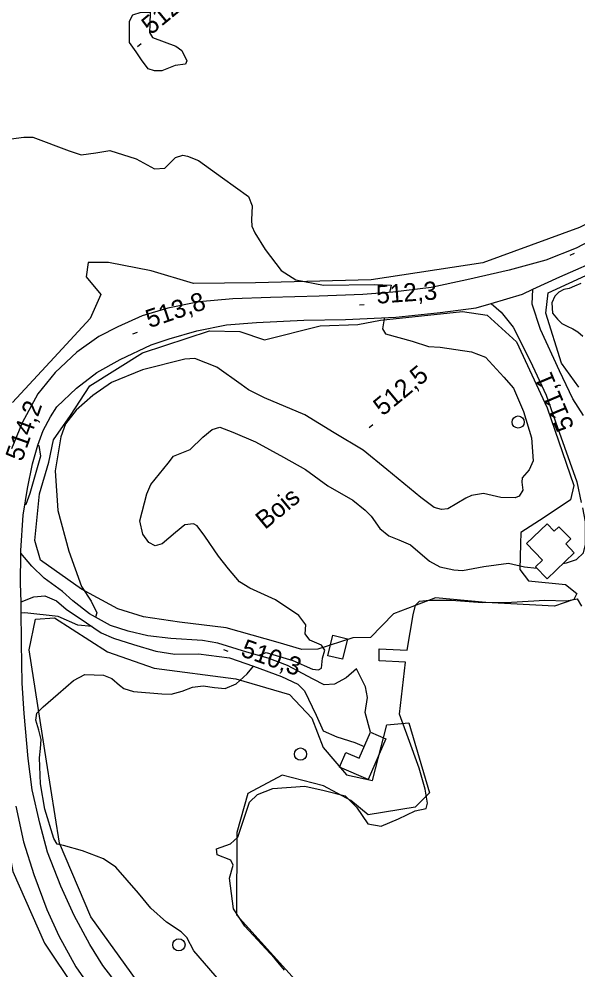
# Model space of a CAD drawing. Extents: x 347059 to 352153, y 6073752 to 6078601.
# Drawn here: x 349153.2 to 349291.1, y 6076824.7 to 6077059.6 of the extents above; entities that cross this region are included whole.
import ezdxf

# ---------------------------------------------------------------- set-up
doc = ezdxf.new("R2010")
doc.units = 0
for name, color, linetype in [('Level 1', 7, 'Continuous'), ('Level 19', 7, 'Continuous'), ('Level 2', 7, 'Continuous'), ('Level 21', 7, 'Continuous'), ('Level 3', 7, 'Continuous'), ('Level 31', 7, 'Continuous'), ('Level 36', 7, 'Continuous'), ('Level 4', 7, 'Continuous'), ('Level 44', 7, 'Continuous')]:
    doc.layers.add(name, color=color, linetype=linetype)

msp = doc.modelspace()

# ---------------------------------------------------------------- linework, layer by layer
at = {"layer": 'Level 1'}
for points in [[(349212.53, 6076902.35), (349212.63, 6076902.53), (349214.21, 6076903.12), (349220.76, 6076901.2), (349220.76, 6076901.2), (349225.61, 6076899.04), (349227.11, 6076898.87), (349227.88, 6076899.29), (349228.1, 6076901.72), (349228.65, 6076903.68), (349227.88, 6076904.98), (349225.01, 6076906.18), (349223.85, 6076907.76), (349223.97, 6076909.96), (349222.27, 6076912.28), (349216.55, 6076916.12), (349210.21, 6076919.07), (349207.66, 6076920.61), (349204.88, 6076923.77), (349202.43, 6076926.97), (349199.09, 6076931.87), (349197.18, 6076934.44), (349196.26, 6076934.88), (349194.1, 6076934.68), (349191.87, 6076932.81), (349188.52, 6076929.99), (349186.78, 6076929.46), (349185.23, 6076930.32), (349183.79, 6076932.34), (349183.05, 6076935.63), (349184.74, 6076942.33), (349185.76, 6076944.67), (349190.05, 6076949.92), (349191.32, 6076951.65), (349195.44, 6076953.24), (349198.58, 6076956.3), (349200.89, 6076958.24), (349202.78, 6076958.76), (349206, 6076957.55), (349211.55, 6076955.2), (349218.45, 6076951.42), (349223.94, 6076948.34), (349229.42, 6076944.31), (349235.61, 6076940.73), (349238.65, 6076938.29), (349240.15, 6076936.84), (349242.24, 6076933.74), (349244.44, 6076931.95), (349246.94, 6076930.94), (349249.79, 6076929.69), (349254.54, 6076925.71), (349257.08, 6076924.33), (349260.48, 6076923.54), (349262.69, 6076923.37), (349267.88, 6076924.36), (349274.01, 6076925.19), (349277.93, 6076924.29), (349281.02, 6076923.96)], [(349287.42, 6076925.09), (349288.32, 6076925.26), (349290.81, 6076926.14), (349292.51, 6076927.79), (349292.98, 6076929.84), (349292.97, 6076935.37), (349292.36, 6076938.9)], [(349209.53, 6076897.84), (349211.1, 6076899.75)], [(349204.27, 6076820.36), (349196.35, 6076829.46), (349194.66, 6076832.77), (349193.24, 6076834.2), (349189.63, 6076836.58), (349185.71, 6076839.99), (349185.71, 6076839.99), (349182.72, 6076843.68), (349177.09, 6076850.15), (349174.03, 6076852.16), (349168.9, 6076854.19), (349164.22, 6076855.52), (349162.62, 6076855.79), (349161.79, 6076857.25), (349159.63, 6076864.47), (349158.55, 6076870.72), (349158.3, 6076877.12), (349158.51, 6076879.45), (349158.66, 6076881.64), (349158.09, 6076883.96), (349157.35, 6076886.44), (349157.65, 6076888.18), (349159.19, 6076889.74), (349162.86, 6076892.97), (349166.68, 6076896.19), (349169.47, 6076897.73), (349174.1, 6076897.58), (349176.09, 6076896.69), (349178.01, 6076895.07), (349179.12, 6076894.24), (349181.49, 6076893.54), (349188.44, 6076892.91), (349190.8, 6076892.87), (349193.45, 6076893.61), (349196.04, 6076894.58), (349198.65, 6076894.89), (349201.42, 6076894.52), (349204.12, 6076894.23), (349206.81, 6076895.41), (349209.53, 6076897.84)]]:
    msp.add_lwpolyline(points, dxfattribs=at)
at = {"layer": 'Level 19'}
for points in [[(349292.55, 6076961.69), (349289.88, 6076965.82), (349286.6, 6076972.67), (349281.89, 6076982.88), (349279.82, 6076989.17), (349280.01, 6076992.83)], [(349269.74, 6076989.34), (349272.17, 6076987.18), (349275.17, 6076983.47), (349279.37, 6076975.15), (349283.31, 6076966.68), (349286.07, 6076958.74), (349290.9, 6076945.32), (349291.97, 6076940.15)], [(349239.94, 6076883.47), (349238.6, 6076888.35), (349239.19, 6076892.06), (349238.69, 6076894.65), (349236.5, 6076899.1), (349233.92, 6076896.88), (349231.09, 6076895.33), (349228.54, 6076895.15), (349225.78, 6076896.59), (349219.48, 6076899.95), (349214.67, 6076901.78), (349209.45, 6076903.19), (349202.28, 6076905.44), (349198.51, 6076906.1), (349190.69, 6076906.61), (349185.04, 6076907.28), (349180.17, 6076908.38), (349175.82, 6076909.83), (349170.62, 6076912.68), (349166.48, 6076915.87), (349163.96, 6076918.19), (349159.46, 6076921.46), (349156.36, 6076924.47), (349153.68, 6076927.66)], [(349153.73, 6076915.62), (349156.86, 6076916.93), (349159.61, 6076917.13), (349162.51, 6076915.88), (349164.89, 6076913.83), (349169.91, 6076910.47), (349173.51, 6076908.02), (349176.53, 6076906.72), (349181.47, 6076905.09), (349186.95, 6076903.45), (349191.65, 6076902.74), (349197.49, 6076902.82), (349205.14, 6076901.8), (349211.11, 6076899.75), (349218.01, 6076897.2), (349222.04, 6076895.32), (349223.68, 6076893.7), (349226.56, 6076887.7), (349228.28, 6076883.82), (349231.61, 6076882.33), (349236.05, 6076880.94), (349238.39, 6076879.89)]]:
    msp.add_lwpolyline(points, dxfattribs=at)
at = {"layer": 'Level 2'}
for points in [[(349182.12, 6077051.51), (349180.49, 6077053.75), (349180.45, 6077059.04), (349181.32, 6077060.59), (349183.38, 6077061.27), (349185.58, 6077061.23), (349185.51, 6077058.25), (349185.41, 6077056.21), (349186.19, 6077054.99), (349191.91, 6077052.87), (349193.36, 6077051.84), (349194.67, 6077049.26), (349194.27, 6077048.39), (349191.75, 6077048.09), (349188.45, 6077046.75), (349186.65, 6077046.75), (349185.11, 6077047.26), (349183.44, 6077049.46), (349182.12, 6077051.51)], [(349146.82, 6077029.41), (349154.42, 6077030.43), (349156.62, 6077030.4), (349165.56, 6077027), (349168.57, 6077026.07), (349172.21, 6077026.56), (349175.64, 6077027.11), (349182.09, 6077025.01), (349186.64, 6077022.59), (349189.22, 6077022.72), (349191.83, 6077025.35), (349193.63, 6077025.96), (349194.83, 6077025.69), (349197.55, 6077024.66), (349203.47, 6077020.4), (349209.85, 6077015.76), (349210.74, 6077013.43), (349210.58, 6077010.01), (349210.64, 6077008.4), (349211.42, 6077006.74), (349213.98, 6077002.66), (349217.9, 6076997.47), (349221.52, 6076995.18), (349228.36, 6076993.86), (349240.96, 6076993.98), (349245.07, 6076993.89), (349244.68, 6076992.03)], [(349291.82, 6076994.3), (349290.31, 6076993.6), (349288.96, 6076993.05), (349287.64, 6076992.82), (349286.45, 6076992.09), (349285.48, 6076991.1), (349284.7, 6076989.53), (349284.83, 6076986.9), (349286.09, 6076985.42), (349287.15, 6076984.36), (349288.48, 6076983.69), (349289.9, 6076983.09), (349291.14, 6076982.34), (349292.36, 6076981.27)], [(349243.4, 6076985.85), (349243.23, 6076985.02), (349242.92, 6076983.04)], [(349242.92, 6076983.04), (349243.67, 6076981.87), (349250.26, 6076980.04), (349254.25, 6076978.74), (349257.17, 6076978.55), (349264.84, 6076977.41), (349268.34, 6076976.06), (349272.85, 6076971.15), (349275.25, 6076968.44), (349277.72, 6076962.65), (349279.65, 6076956.18)], [(349208.02, 6076969.36), (349202.05, 6076973.64), (349196.57, 6076975.76), (349194.12, 6076975.58), (349183.65, 6076972.96), (349176.08, 6076969.81), (349171.46, 6076966.58), (349167.31, 6076962.95), (349164.66, 6076959.64), (349163.57, 6076956.43), (349162.1, 6076948.04), (349162.79, 6076938.24), (349165.51, 6076928.13), (349168.65, 6076919.45), (349171.05, 6076915.81), (349172.46, 6076912.91), (349172.12, 6076911.86)], [(349279.65, 6076956.18), (349280.1, 6076950.49), (349279.07, 6076948.22), (349277.42, 6076946.24), (349277.29, 6076945.23), (349277.55, 6076943.2), (349276.68, 6076941.73), (349275.66, 6076941.33), (349272.13, 6076941.44), (349267.83, 6076942.41), (349264.85, 6076941.94), (349263.45, 6076941.29), (349259.04, 6076938.58), (349257.44, 6076938.44), (349255.7, 6076938.92), (349252.35, 6076941.44), (349243.95, 6076948.33), (349238.15, 6076953.07), (349230.98, 6076957.41), (349223.78, 6076961.86), (349213.81, 6076966.04), (349209.84, 6076968.04), (349208.02, 6076969.36)], [(349157.82, 6076954.28), (349158.14, 6076954.23), (349158.55, 6076951.66), (349155.91, 6076942.42), (349154.93, 6076939.65), (349154.64, 6076939.64)], [(349171.3, 6076909.53), (349167.74, 6076909.92), (349162.92, 6076912.06), (349154.64, 6076912.91), (349153.8, 6076912.88)]]:
    msp.add_lwpolyline(points, dxfattribs=at)
at = {"layer": 'Level 21'}
for points in [[(349298.98, 6077007.35), (349290.67, 6077002.95), (349283.19, 6076999.99), (349274.16, 6076997.54), (349263.75, 6076995.13), (349254.91, 6076993.27), (349245.43, 6076992.09), (349238.05, 6076991.53), (349227.26, 6076991.12), (349215.26, 6076990.82), (349206, 6076990.48), (349197.67, 6076989.72), (349189.96, 6076988.21), (349183.59, 6076986.26), (349177.57, 6076983.54), (349172.91, 6076981.14), (349167.47, 6076977.34), (349162.12, 6076972.27), (349157.89, 6076967.02), (349154.02, 6076959.89), (349151.39, 6076953.43)], [(349197.07, 6076982.6), (349204.41, 6076984.02), (349211.83, 6076984.61), (349223.52, 6076985.19), (349233.8, 6076985.4), (349246.24, 6076985.99), (349257.18, 6076987.12), (349266.04, 6076988.24), (349269.74, 6076989.34), (349277.44, 6076991.62), (349280.01, 6076992.83), (349286.64, 6076995.95), (349297.93, 6077000.89)], [(349176.15, 6076822.94), (349173.89, 6076825.84), (349170.66, 6076831), (349166.84, 6076838.21), (349163.51, 6076845.46), (349160.25, 6076853.82), (349158.38, 6076861.02), (349156.49, 6076869.25), (349155.49, 6076876.95), (349154.47, 6076888.09), (349154.02, 6076895.58), (349153.87, 6076905.41), (349153.79, 6076913.88), (349153.73, 6076915.62), (349153.56, 6076920.2), (349153.68, 6076927.66), (349153.7, 6076928.32), (349154.21, 6076937.05), (349155.31, 6076943.65), (349156.52, 6076949.75), (349157.84, 6076954.37), (349159.19, 6076957.97), (349160.97, 6076961.32), (349162.58, 6076963.79), (349167.44, 6076968.45), (349172.43, 6076972.25), (349178.18, 6076975.49), (349185.85, 6076979.13), (349190.3, 6076980.6), (349197.07, 6076982.6)], [(349152.45, 6076865.22), (349154.29, 6076856.42), (349156.84, 6076848.3), (349160.08, 6076839.7), (349163.03, 6076833.18), (349167.25, 6076825.48), (349171.46, 6076819.5)]]:
    msp.add_lwpolyline(points, dxfattribs=at)
at = {"layer": 'Level 3'}
for p, q in [((349182.44, 6077052.8), (349183.36, 6077053.57)), ((349289.2, 6077001.3), (349290.3, 6077001.77)), ((349237.22, 6076989.02), (349238.42, 6076989.1)), ((349181.3, 6076981.84), (349182.44, 6076982.23)), ((349239.63, 6076958.67), (349240.55, 6076959.44)), ((349203.64, 6076903.85), (349204.78, 6076903.45))]:
    msp.add_line(p, q, dxfattribs=at)
at = {"layer": 'Level 31'}
for points in [[(349282.36, 6076925.92), (349278.43, 6076930.03), (349283.54, 6076934.92), (349285.29, 6076933.09), (349286.46, 6076934.2), (349289.35, 6076931.18), (349288.12, 6076930), (349290.24, 6076927.78), (349283.51, 6076921.35), (349280.68, 6076924.32), (349282.36, 6076925.92)], [(349234.3, 6076906.55), (349233.06, 6076901.47), (349229.45, 6076902.36), (349230.69, 6076907.44), (349234.3, 6076906.55)], [(349243.73, 6076881.84), (349239.38, 6076871.77), (349232.28, 6076874.84), (349233.85, 6076878.46), (349237.16, 6076877.03), (349239.94, 6076883.47), (349243.73, 6076881.84)]]:
    msp.add_lwpolyline(points, dxfattribs=at)
at = {"layer": 'Level 36'}
for centre in [(349276.38, 6076960.05), (349222.7, 6076878.06), (349192.68, 6076830.96)]:
    msp.add_circle(centre, 1.5, dxfattribs=at)
at = {"layer": 'Level 4'}
for points in [[(349247.08, 6076887.89), (349247.08, 6076887.89), (349248.6, 6076900.79), (349242.09, 6076901.05), (349242.08, 6076904.04), (349249.03, 6076903.7), (349250.46, 6076912.47), (349251.04, 6076914.83), (349252.07, 6076915.85), (349253.72, 6076916.02), (349255.16, 6076916.1), (349259.93, 6076916.04), (349267.56, 6076915.51), (349274.77, 6076915.57), (349282.97, 6076916.06), (349288.35, 6076915.9), (349290.92, 6076916.41), (349292, 6076914.57)], [(349218.7, 6076824.73), (349216.28, 6076827.65), (349208.93, 6076835.6), (349206.14, 6076839.87), (349205.12, 6076847.42), (349206.07, 6076850.61), (349205.46, 6076851.9), (349202.14, 6076853.18), (349201.96, 6076854.67), (349205.42, 6076855.92), (349207.2, 6076857.56), (349210.12, 6076866.15), (349212.1, 6076868.1), (349215.83, 6076869.56), (349223.72, 6076870.16), (349228.52, 6076869.07), (349233.7, 6076867.71), (349236.46, 6076864.91), (349239.26, 6076860.81), (349242.56, 6076860.27), (349246.89, 6076862.09), (349250.99, 6076864.01), (349253.65, 6076864.59), (349254.02, 6076865.95), (349253.44, 6076869.36), (349251.97, 6076874.58), (349249.23, 6076882.04), (349247.08, 6076887.89)]]:
    msp.add_lwpolyline(points, dxfattribs=at)
at = {"layer": 'Level 44'}
for points in [[(349369, 6077061.91), (349360.47, 6077049.19), (349351.1, 6077040.87), (349336.31, 6077029.35), (349315.09, 6077019.69), (349291.53, 6077008.06), (349267.67, 6076999.4), (349240.13, 6076995.19), (349211.55, 6076994.39), (349196.31, 6076994.28), (349185.87, 6076997.36), (349175.32, 6076999.46), (349170.27, 6076999.43), (349169.78, 6076995.88), (349173.37, 6076991.55), (349170.79, 6076985.65), (349161.93, 6076976), (349151.62, 6076964.84)], [(349291.36, 6076968.69), (349287.1, 6076974.56), (349283.2, 6076986.94), (349283.76, 6076991.97), (349298.25, 6076998.66)], [(349242.45, 6076985.22), (349262.67, 6076987.31), (349268.78, 6076986.43), (349275.99, 6076979.88), (349283.51, 6076963.57), (349290.12, 6076944.4), (349289.3, 6076940.87), (349282.79, 6076936.48), (349277.07, 6076932.74), (349276.97, 6076929.97), (349276.8, 6076923.68), (349278.98, 6076920.87), (349288.11, 6076919.96), (349290.84, 6076917.74), (349290.13, 6076916.25), (349285.4, 6076914.55), (349268.45, 6076915.51), (349255.99, 6076916.64), (349245.66, 6076912.66), (349239.99, 6076906.86), (349235.57, 6076906.77), (349226.99, 6076903.94), (349223.05, 6076903.88), (349217.17, 6076905.61), (349204.34, 6076909.27), (349192.85, 6076910.65), (349183.9, 6076911.99), (349177.64, 6076913.95), (349168.64, 6076918.81), (349158.48, 6076925.93), (349157.09, 6076930.84), (349158.28, 6076942.35), (349160.58, 6076950.13), (349161.76, 6076955.67), (349165.89, 6076961.67), (349170.72, 6076969), (349183.68, 6076977.14), (349200.21, 6076982.59), (349207.67, 6076982.4), (349213.83, 6076980.37), (349227.57, 6076983.78), (349236.8, 6076984.17), (349242.45, 6076985.22)], [(349155.76, 6076903.77), (349157.29, 6076911.4), (349162.01, 6076911.73), (349175.07, 6076903.27), (349186.59, 6076899.24), (349206.75, 6076896.64), (349219.95, 6076892.75), (349225.47, 6076886.91), (349228.3, 6076879.7), (349234.04, 6076872.96), (349240.43, 6076871.56), (349243.98, 6076885.32), (349249.41, 6076885.81), (349254.49, 6076868.48), (349250.99, 6076864.95), (349239.39, 6076863.05), (349235.08, 6076866.63), (349228.39, 6076870.19), (349218.12, 6076872.83), (349209.71, 6076868.35), (349206.94, 6076858.7), (349206.86, 6076838.4), (349222.09, 6076821.48)], [(349182.39, 6076821.98), (349170.91, 6076837.88), (349163.19, 6076856.04), (349159.99, 6076876.28), (349155.76, 6076903.77)], [(349120.99, 6076803.23), (349124.88, 6076834.93), (349123.22, 6076845.22), (349111.27, 6076841.22), (349102.07, 6076840.42), (349091.23, 6076852.03), (349094.06, 6076859.79), (349116.46, 6076878.22), (349129.58, 6076873.6), (349140.28, 6076876.56), (349143.84, 6076874.44), (349147.83, 6076869.35), (349151.7, 6076849.05), (349159.47, 6076831.34), (349167.17, 6076819.94)]]:
    msp.add_lwpolyline(points, dxfattribs=at)

# ---------------------------------------------------------------- texts
at = {"layer": 'Level 3'}
for s, rotation, p in [('512,2', 39.62, (349185.8, 6077055.52)), ('512,3', 4.0969, (349241.52, 6076989.27)), ('513,8', 18.8164, (349185.4, 6076983.2)), ('512,5', 39.62, (349242.99, 6076961.38)), ('511,1', 112.7435, (349290.31, 6076958.88)), ('514,2', 70.4434, (349153.96, 6076950.1)), ('510,3', 340.3928, (349207.7, 6076902.34))]:
    msp.add_text(s, height=4.5, rotation=rotation, dxfattribs=at).set_placement(p)
at = {"layer": 'Level 44'}
msp.add_text('Bois', height=4.5, rotation=39.568, dxfattribs=at).set_placement((349213.93, 6076933.36))

doc.saveas('drawing.dxf')
